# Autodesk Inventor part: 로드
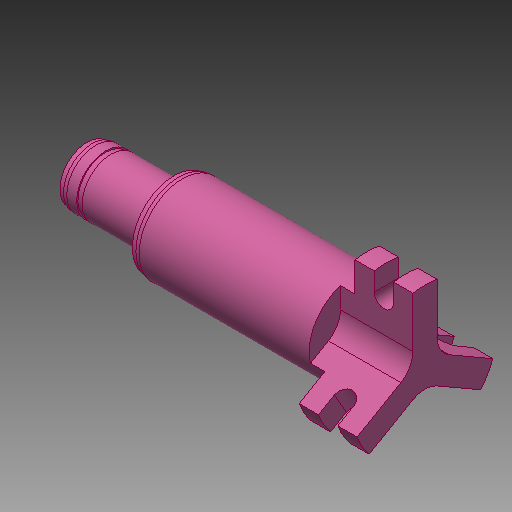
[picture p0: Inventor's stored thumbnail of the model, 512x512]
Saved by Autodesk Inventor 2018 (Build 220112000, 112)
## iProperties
Created: 2020-02
Part Number: 로드
Material: 강철, 연강
Document SubType Name: Modeling
Designer: mduedu
Density: 1 g/cm^3
Appearance: 분홍색
Author: mduedu
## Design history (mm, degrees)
sketch "스케치1"
  geometry: L1 (0, 0)-(-12, 0); L2 (-12, 0)-(-12, 15); L3 (-12, 15)-(0, 15); L4 (0, 15)-(0, 0); L5 (-12, 0)-(-52, 0); L6 (-52, 0)-(-52, 9); L7 (-52, 9)-(-12, 9); L8 (-12, 9)-(-12, 0); L9 (-52, 0)-(-70, 0); L10 (-70, 0)-(-70, 6); L11 (-70, 6)-(-52, 6); L12 (-52, 6)-(-52, 0)
  constraints: 24 end point, 6 parallel, 3 horizontal, 3 perpendicular
  dimensions: "d0" = 70 distance between parallel lines of L4 L10; "d2" = 18 distance of L10.end L11.end; "d3" = 40 distance of L6.end L7.end; "d4" = 12 diameter of L11 L9; "d5" = 18 diameter of L7 L5; "d6" = 30 diameter of L3 L1
revolve "회전1" sketch "스케치1" stored, may be unused: angle "d7" = 90 deg
chamfer "모따기1" distance "d8" = 1.4; stored, may be unused: second distance "d9" = 2, angle "d10" = 15 deg
fillet "모깎기1" dims "d11" = 3
chamfer "모따기2" distance "d12" = 1.4; stored, may be unused: second distance "d13" = 2, angle "d14" = 15 deg
fillet "모깎기2" dims "d15" = 3
sketch "스케치2"
  geometry: L1 (50.981, 8.898)-(52, 8.625) reference; L2 (52, 8.625)-(52, 6) reference; L3 (52, 6)-(68.205, 6) reference; L4 (68.981, 5.898)-(70, 5.625) reference; L5 (70, 5.625)-(70, -5.625) reference; L6 (70, -5.625)-(68.981, -5.898) reference; L7 (68.205, -6)-(52, -6) reference; L8 (52, -6)-(52, -8.625) reference; L9 (52, -8.625)-(50.981, -8.898) reference; L10 (50.205, -9)-(12, -9) reference; L11 (12, -9)-(12, -15) reference; L12 (12, -15)-(0, -15) reference; L13 (0, -15)-(0, 15) reference; L14 (0, 15)-(12, 15) reference; L15 (12, 15)-(12, 9) reference; L16 (12, 9)-(50.205, 9) reference; L17 (0, 0)-(70, 0); L18 (65, 6)-(66.15, 6); L19 (66.15, 6)-(66.15, 5.75); L20 (66.15, 5.75)-(65, 5.75); L21 (65, 5.75)-(65, 6); A1 r 3 centre (50.205, 6) between (50.981, 8.898) and (50.205, 9) reference; A2 r 3 centre (68.205, 3) between (68.981, 5.898) and (68.205, 6) reference; A3 r 3 centre (68.205, -3) between (68.205, -6) and (68.981, -5.898) reference; A4 r 3 centre (50.205, -6) between (50.205, -9) and (50.981, -8.898) reference
  constraints: 10 end point, 2 parallel, 1 horizontal, 1 midpoint, 1 perpendicular, 1 point on line
  dimensions: "d16" = 13 distance between parallel lines of L21 L2; "d17" = 1.15 distance of L18.start L18.end; "d18" = 11.5 diameter of L20 L17
revolve "회전2" sketch "스케치2" stored, may be unused: angle "d19" = 90 deg
sketch "스케치3"
  geometry: L1 (0, 0)-(-15, 0); L2 (0, 0)-(7.5, -12.99); L3 (0, 0)-(7.5, 12.99); L4 (-1.443, -2.5)-(-14.79, -2.5); L5 (-1.443, 2.5)-(-14.79, 2.5); L6 (-1.443, -2.5)-(5.23, -14.059); L7 (2.887, 0)-(9.56, -11.559); L8 (2.887, 0)-(9.56, 11.559); L9 (-1.443, 2.5)-(5.23, 14.059); C1 r 15 at (0, 0) reference; 1 further point
  constraints: 18 end point, 6 parallel, 1 coincident, 1 horizontal, 15 other
  dimensions: "d20" = 120 deg angle of L2 L1; "d21" = 120 deg angle of L3 L1; "d22" = 5 distance between parallel lines of L5 L4; "d24" = 5 distance between parallel lines of L7 L6; "d25" = 5 distance between parallel lines of L9 L8
extrude "돌출1" cut sketch "스케치3" distance "d26" = 15; taper "d27" = 0 deg
fillet "모깎기3" dims "d28" = 5
sketch "스케치4"
  geometry: L1 (4, 21)-(8, 21); L2 (8, 21)-(8, 11); L3 (8, 11)-(4, 11); L4 (4, 11)-(4, 21); 2 further points
  constraints: 8 end point, 2 parallel, 1 horizontal, 1 horizontal alignment, 1 midpoint, 1 perpendicular, 2 other
  dimensions: "d29" = 11 distance from line of L3 point (0, 0); "d30" = 4 distance of L1.start L1.end; "d31" = 6 horizontal distance of point (6, 11) point (0, 0); "d32" = 10 distance between parallel lines of L1 L3
extrude "돌출2" cut sketch "스케치4" extent not by distance; stored distance "d33" = 15; taper "d34" = 0 deg
node "솔리드1"
pattern_circular "원형 패턴1" dims angle "d36" = 360 deg
node "투영된 루프1"
node "절단 모서리 투영1"
